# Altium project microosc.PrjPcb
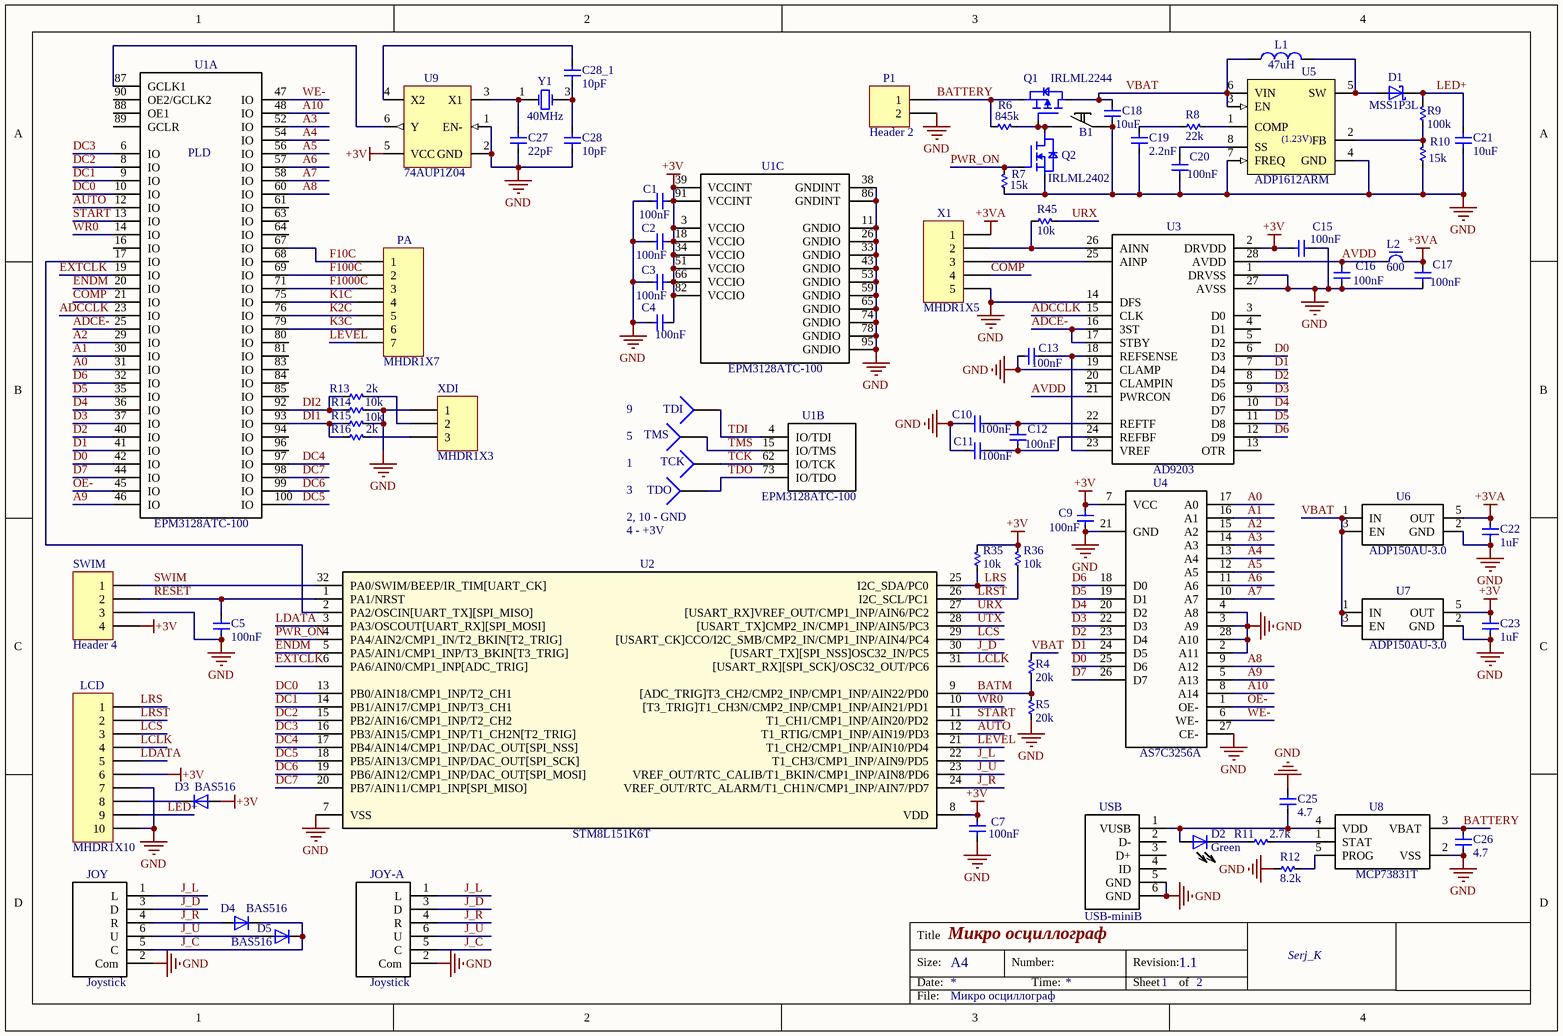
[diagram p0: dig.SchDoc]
2 sheets, 144 parts. Net scope: global (net labels, ports and power ports of the same name join across sheets).
Board file: microosc.PcbDoc
Sheets:
  dig.SchDoc
  analog.SchDoc

## Sheet dig.SchDoc: Микро осциллограф
size A4; Author: Serj_K; Engineer: Serj_K; Organization: Serj_K; Revision: 1.1; SheetNumber: 1; SheetTotal: 2; PageSetup: Record=PageOptions|CenterHorizontal=True|CenterVertical=True|PrintScale=1.00|XCorrection=1.00|YCorrection=1.00|PrintKind=0|BorderSize=5000000|LeftOffset=0|BottomOffset=0|Orientation=2|PaperLength=1000|PaperWidth=1000|Scale=100|PaperSource=7|PrintQuality=1200|MediaType=1|DitherType=10|PaperKind=A4|PrintScaleMode=1

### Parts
B1  Micro Button  [Micro Button]  (value not drawn)
C1  value 100nF  [C0603NH080]  (hidden comment: Cap)
C2  value 100nF  [C0603NH080]  (hidden comment: Cap)
C3  value 100nF  [C0603NH080]  (hidden comment: Cap)
C4  value 100nF  [C0603NH080]  (hidden comment: Cap)
C5  value 100nF  [C0603NH080]  (hidden comment: Cap)
C7  value 100nF  [C0603NH080]  (hidden comment: Cap)
C9  value 100nF  [C0603NH080]  (hidden comment: Cap)
C10  value 100nF  [C0603NH080]  (hidden comment: Cap)
C11  value 100nF  [C0603NH080]  (hidden comment: Cap)
C12  value 100nF  [C0603NH080]  (hidden comment: Cap)
C13  value 100nF  [C0603NH080]  (hidden comment: Cap)
C15  value 100nF  [C0603NH080]  (hidden comment: Cap)
C16  value 100nF  [C0603NH080]  (hidden comment: Cap)
C17  value 100nF  [C0603NH080]  (hidden comment: Cap)
C18  value 10uF  [C0805NH145]  (hidden comment: Cap)
C19  value 2.2nF  [C0805NH145]  (hidden comment: Cap)
C20  value 100nF  [C0603NH080]  (hidden comment: Cap)
C21  value 10uF  [C1206NH190]  (hidden comment: Cap)
C22  value 1uF  [C0805NH145]  (hidden comment: Cap)
C23  value 1uF  [C0805NH145]  (hidden comment: Cap)
C25  value 4.7  [C0805NH145]  (hidden comment: Cap)
C26  value 4.7  [C0805NH145]  (hidden comment: Cap)
C27  value 22pF  [C0603NH080]  (hidden comment: Cap)
C28  value 10pF  [C0603NH080]  (hidden comment: Cap)
C28_1  value 10pF  [C0603NH080]  (hidden comment: Cap)
D1  Part Label: MSS1P3L  [SOD323FL_VISHAY_MICROSMP]  (hidden comment: D_Schottky)
D2  Green  [SvetoDiod-D3]
D3  Part Label: BAS516  [SOD523]  (hidden comment: Diode)
D4  Part Label: BAS516  [SOD523]  (hidden comment: Diode)
D5  Part Label: BAS516  [SOD523]  (hidden comment: Diode)
JOY  Joystick  [Joystick]
JOY-A  Joystick  [Joystick]
L1  value 47uH  [L1212_muR_LQH3NP]  (hidden comment: L)
L2  value 600  [C0603NH080]  (hidden comment: BEAD)
LCD  MHDR1X10  [MHDR1X10]
P1  Header 2  [HDR1X2]
PA  MHDR1X7  [MHDR1X7]
Q1  IRLML2244  [SOT23-3_DISCRETE]
Q2  IRLML2402  [SOT23-3_DISCRETE]
R4  value 20k  [R0603N]  (hidden comment: R)
R5  value 20k  [R0603N]  (hidden comment: R)
R6  value 845k  [R0603N]  (hidden comment: R)
R7  value 15k  [R0603N]  (hidden comment: R)
R8  value 22k  [R0603N]  (hidden comment: R)
R9  value 100k  [R0603N]  (hidden comment: R)
R10  value 15k  [R0603N]  (hidden comment: R)
R11  value 2.7k  [R0805NH070]  (hidden comment: R)
R12  value 8.2k  [R0603N]  (hidden comment: R)
R13  value 2k  [R0603N]  (hidden comment: R)
R14  value 10k  [R0603N]  (hidden comment: R)
R15  value 10k  [R0603N]  (hidden comment: R)
R16  value 2k  [R0603N]  (hidden comment: R)
R35  value 10k  [R0603N]  (hidden comment: R)
R36  value 10k  [R0603N]  (hidden comment: R)
R45  value 10k  [R0603N]  (hidden comment: R)
SWIM  Header 4  [HDR1X4]
TCK  Socket  [PIN1]  (value not drawn)
TDI  Socket  [PIN1]  (value not drawn)
TDO  Socket  [PIN1]  (value not drawn)
TMS  Socket  [PIN1]  (value not drawn)
U1  EPM3128ATC-100  [TQFP100_N]  (parts A,B,C of 3)
U2  STM8L151K6T  [TQFP32_L]
U3  AD9203  [RS-28]
U4  AS7C3256A  [TSOP28]
U5  Part Label: ADP1612ARM  [MSOP8]  (hidden comment: ADP1612)
U6  ADP150AU-3.0  [RT-5]
U7  ADP150AU-3.0  [RT-5]
U8  MCP73831T  [S5]
U9  74AUP1Z04  [SC70-6]
USB  USB-miniB  [USB-B_CrossBoard]
X1  MHDR1X5  [MHDR1X5]
XDI  MHDR1X3  [MHDR1X3]
Y1  value 40MHz  [QUARZ_REC_25x32]  (hidden comment: Quarz Rezonator SMD)

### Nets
+3V: C1.2 C2.2 C3.2 C4.2 C7.2 C9.1 C15.2 C23.2 D3.A LCD.6 R35.2 R36.2 SWIM.4 U1.3(VCCIO) U1.18(VCCIO) U1.34(VCCIO) U1.39(VCCINT) U1.51(VCCIO) U1.66(VCCIO) U1.82(VCCIO) U1.91(VCCINT) U2.8(VDD) U3.2(DRVDD) U4.7(VCC) U7.5(OUT) U9.5(VCC)
+3VA: C17.1 C22.2 L2.2 U6.5(OUT) X1.1
GND: B1.1 C1.1 C2.1 C3.1 C4.1 C5.1 C7.1 C9.2 C10.1 C11.1 C13.1 C15.1 C16.2 C17.2 C18.1 C19.1 C20.2 C21.1 C22.1 C23.1 C25.2 C26.1 C27.1 C28.1 JOY.2(Com) JOY-A.2(Com) LCD.7 LCD.10 P1.2 Q2.2(S) R5.1 R7.1 R10.1 R12.1 R14.2 R15.2 SWIM.3 U1.11(GNDIO) U1.26(GNDIO) U1.33(GNDIO) U1.38(GNDINT) U1.43(GNDIO) U1.53(GNDIO) U1.59(GNDIO) U1.65(GNDIO) U1.74(GNDIO) U1.78(GNDIO) U1.86(GNDINT) U1.95(GNDIO) U2.7(VSS) U3.1(DRVSS) U3.14(DFS) U3.19(CLAMP) U3.27(AVSS) U4.2(A11) U4.3(A9) U4.4(A8) U4.21(GND) U4.27(CE-) U4.28(A10) U5.4(GND) U5.7(FREQ) U6.2(GND) U7.2(GND) U8.2(VSS) U9.1(EN-) U9.2(GND) USB.5(GND) USB.6(GND) X1.5 XDI.1
A0: U1.31(IO) U4.17(A0)
A1: U1.30(IO) U4.16(A1)
A2: U1.29(IO) U4.15(A2)
A3: U1.52(IO) U4.14(A3)
A4: U1.54(IO) U4.13(A4)
A5: U1.56(IO) U4.12(A5)
A6: U1.57(IO) U4.11(A6)
A7: U1.58(IO) U4.10(A7)
A8: U1.60(IO) U4.9(A12)
A9: U1.46(IO) U4.5(A13)
A10: U1.48(IO) U4.8(A14)
ADCCLK: U1.23(IO) U3.15(CLK)
ADCE-: U1.25(IO) U3.16(3ST) U3.17(STBY)
AUTO: U1.12(IO) U2.12(T1_RTIG/CMP1_INP/AIN19/PD3)
AVDD: C16.1 L2.1 U3.21(PWRCON) U3.28(AVDD)
BATM: R4.1 R5.2 U2.9([ADC_TRIG]T3_CH2/CMP2_INP/CMP1_INP/AIN22/PD0)
BATTERY: C26.2 P1.1 Q1.2(S) R6.1 U8.3(VBAT)
COMP: U1.21(IO) X1.4
D0: U1.42(IO) U3.6(D3) U4.25(D6)
D1: U1.41(IO) U3.7(D4) U4.24(D5)
D2: U1.40(IO) U3.8(D5) U4.23(D4)
D3: U1.37(IO) U3.9(D6) U4.22(D3)
D4: U1.36(IO) U3.10(D7) U4.20(D2)
D5: U1.35(IO) U3.11(D8) U4.19(D1)
D6: U1.32(IO) U3.12(D9) U4.18(D0)
D7: U1.44(IO) U4.26(D7)
DC0: U1.10(IO) U2.13(PB0/AIN18/CMP1_INP/T2_CH1)
DC1: U1.9(IO) U2.14(PB1/AIN17/CMP1_INP/T3_CH1)
DC2: U1.8(IO) U2.15(PB2/AIN16/CMP1_INP/T2_CH2)
DC3: U1.6(IO) U2.16(PB3/AIN15/CMP1_INP/T1_CH2N[T2_TRIG])
DC4: U1.97(IO) U2.17(PB4/AIN14/CMP1_INP/DAC_OUT[SPI_NSS])
DC5: U1.100(IO) U2.18(PB5/AIN13/CMP1_INP/DAC_OUT[SPI_SCK])
DC6: U1.99(IO) U2.19(PB6/AIN12/CMP1_INP/DAC_OUT[SPI_MOSI])
DC7: U1.98(IO) U2.20(PB7/AIN11/CMP1_INP[SPI_MISO])
DI1: R15.1 R16.1 U1.93(IO)
DI2: R13.1 R14.1 U1.92(IO)
ENDM: U1.20(IO) U2.5(PA5/AIN1/CMP1_INP/T3_BKIN[T3_TRIG])
EXTCLK: U1.19(IO) U2.6(PA6/AIN0/CMP1_INP[ADC_TRIG])
F10C: PA.1 U1.67(IO)
F100C: PA.2 U1.69(IO)
F1000C: PA.3 U1.71(IO)
J_C: D4.C D5.C JOY.5(C) JOY-A.5(C)
J_D: JOY.3(D) JOY-A.3(D) U2.30([USART_TX][SPI_NSS]OSC32_IN/PC5)
J_L: JOY.1(L) JOY-A.1(L) U2.22(T1_CH3/CMP1_INP/AIN9/PD5)
J_R: D4.A JOY.4(R) JOY-A.4(R) U2.24(VREF_OUT/RTC_ALARM/T1_CH1N/CMP1_INP/AIN7/PD7)
J_U: D5.A JOY.6(U) JOY-A.6(U) U2.23(VREF_OUT/RTC_CALIB/T1_BKIN/CMP1_INP/AIN8/PD6)
K1C: PA.4 U1.75(IO)
K2C: PA.5 U1.76(IO)
K3C: PA.6 U1.79(IO)
LCLK: LCD.4 U2.31([USART_RX][SPI_SCK]/OSC32_OUT/PC6)
LCS: LCD.3 U2.29([USART_CK]CCO/I2C_SMB/CMP2_IN/CMP1_INP/AIN4/PC4)
LDATA: LCD.5 U2.3(PA3/OSCOUT[UART_RX][SPI_MOSI])
LED+: C21.2 D1.C LCD.9 R9.2
LEVEL: PA.7 U2.21(T1_CH2/CMP1_INP/AIN10/PD4)
LRS: LCD.1 R35.1 U2.25(I2C_SDA/PC0)
LRST: LCD.2 R36.1 U2.26(I2C_SCL/PC1)
OE-: U1.45(IO) U4.1(OE-)
PWR_ON: Q2.1(G) R7.2 U2.4(PA4/AIN2/CMP1_IN/T2_BKIN[T2_TRIG])
RESET: C5.2 SWIM.2 U2.1(PA1/NRST)
START: U1.13(IO) U2.11(T1_CH1/CMP1_INP/AIN20/PD2)
SWIM: SWIM.1 U2.32(PA0/SWIM/BEEP/IR_TIM[UART_CK])
TCK: TCK.1 U1.62(IO/TCK)
TDI: TDI.1 U1.4(IO/TDI)
TDO: TDO.1 U1.73(IO/TDO)
TMS: TMS.1 U1.15(IO/TMS)
URX: R45.2 U2.27([USART_RX]VREF_OUT/CMP1_INP/AIN6/PC2)
UTX: U2.28([USART_TX]CMP2_IN/CMP1_INP/AIN5/PC3)
VBAT: C18.2 L1.1 Q1.3(D) R4.2 U5.3(EN) U5.6(VIN) U6.1(IN) U6.3(EN) U7.1(IN) U7.3(EN)
WE-: U1.47(IO) U4.6(WE-)
WR0: U1.14(IO) U2.10([T3_TRIG]T1_CH3N/CMP2_INP/CMP1_INP/AIN21/PD1)
NetB1_2: B1.2 Q1.1(G) Q2.3(D) R6.2
NetC10_2: C10.2 C12.2 U3.22(REFTF)
NetC11_2: C11.2 C12.1 U3.24(REFBF)
NetC13_2: C13.2 U3.18(REFSENSE) U3.23(VREF)
NetC19_2: C19.2 R8.1
NetC20_1: C20.1 U5.8(SS)
NetC25_1: C25.1 D2.A U8.4(VDD) USB.1(VUSB)
NetC27_2: C27.2 U9.3(X1) Y1.1(OSC1)
NetC28_1_1: C28_1.1 U9.4(X2)
NetC28_2: C28.2 C28_1.2 Y1.3(OSC2)
NetD1_A: D1.A L1.2 U5.5(SW)
NetD2_K: D2.K R11.1
NetD3_C: D3.C LCD.8
NetR8_2: R8.2 U5.1(COMP)
NetR9_1: R9.1 R10.2 U5.2(FB)
NetR11_2: R11.2 U8.1(STAT)
NetR12_2: R12.2 U8.5(PROG)
NetR13_2: R13.2 XDI.2
NetR16_2: R16.2 XDI.3
NetR45_1: R45.1 U3.26(AINN) X1.2
NetU1_17: U1.17(IO) U2.2(PA2/OSCIN[UART_TX][SPI_MISO])
NetU1_87: U1.87(GCLK1) U9.6(Y)
NetU3_25: U3.25(AINP) X1.3

Not connected (* = marked no-connect by the designer): U1 16(IO) 61(IO) 63(IO) 64(IO) 68(IO) 80(IO) 81(IO) 83(IO) 84(IO) 85(IO) 88(OE1) 89(GCLR) 90(OE2/GCLK2) 94(IO) 96(IO); U3 3(D0) 4(D1) 5(D2) 13(OTR) 20(CLAMPIN); USB 2(D-) 3(D+) 4(ID)

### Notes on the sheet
- 9
- 5
- 1
- 3
- (near TDO) 2, 10 - GND
- 4 - +3V

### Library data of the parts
C1-C5 C7 C9-C13 C15-C17 C20 = CL10B104KB8NNNC: PartName: CL10; Part Label: C0603 100nF 10% X7R 50V; Manufacturer: Samsung Electro-Mechanics; Voltage: 50V; Tolerance: 10 %; Device: C; ShortName: C0603
C18 = GRM21BR61A106KE19L: PartName: GRM21; Part Label: C0805 10uF 10% X5R 10V; Manufacturer: muRata; Voltage: 10V; Tolerance: 10 %; Device: C; ShortName: C0805
C19 = CL21C222JBFNNNE: PartName: CL21; Part Label: C0805 2.2nF 5% NP0 50V; Manufacturer: Samsung Electro-Mechanics; Voltage: 50V; Tolerance: 5 %; Device: C; ShortName: C0805
C21 = GRM31CR61E106KA12L: PartName: GRM31; Part Label: C1206 10uF 10% X5R 25V; Manufacturer: muRata; Voltage: 25V; Tolerance: 10 %; Device: C; ShortName: C1206
C22 C23 C25 C26 = GRM21BR71H105KA12L: PartName: GRM21; Part Label: C0805 1uF 10% X7R 50V; Manufacturer: muRata; Voltage: 50V; Tolerance: 10 %; Device: C; ShortName: C0805
C27 C28 C28_1 = CL10C220JB8NNNC: PartName: CL10; Part Label: C0603 22pF 5% NP0 50V; Manufacturer: Samsung Electro-Mechanics; Voltage: 50V; Tolerance: 5 %; Device: C; ShortName: C0603
D1 = MSS1P3L-M3/89A: 30V, 1A, eSMP, Surface Mount Schottky Barrier Rectifiers; PartName: MSSXPXX; Manufacturer: Vishay; ClassName_u: Schottky SMD; Device: D
D2 = Svetodiod: Lite Diode
D3-D5 = BAS516,115: High-speed switching diodes; Manufacturer: NXP Semiconductors; ClassName_u: Switching SMD; Device: D
L1 = LQH3NPN470MM0L: Shielded Power Inductor Wire Wound; Part Label: L1212 47uH 20% 0.31A; Manufacturer: muRata; Tolerance: 20 %; ShortName: L1212
L2 = BLM18KG601SN1D: High performance type for power lines up to 600ohm.; Part Label: SMD Beads 600 1.3A; Manufacturer: muRata; Device: EMI; ShortName: SMD Beads
LCD = MHDR1X10: Header, 10-Pin
P1 = Header 2: Header, 2-Pin
PA = MHDR1X7: Header, 7-Pin
Q1 = IRLML2244TRPBF: 20V, 4.3A Single P-Channel HEXFET Power MOSFET; Manufacturer: International Rectifier; Device: Q; ShortName: PMOS
Q2 = IRLML2402TRPBF: 20V, 0.25 Ohm, Single N-Channel HEXFET Power MOSFET; Manufacturer: International Rectifier; Device: Q; ShortName: NMOS
R4 R5 = 0603SAF2002T50: PartName: 0603SA; Part Label: R0603 20k 1% TC100 50V; Manufacturer: uniOhm; TempCo: 100 ppm; Tolerance: 1 %; ShortName: R0603
R6 = ERJ3EKF8453V: PartName: ERJ3E; Part Label: R0603 845k 1% TC100 50V; Manufacturer: Panasonic; TempCo: 100 ppm; Tolerance: 1 %; ShortName: R0603
R7 R10 = 0603SAF1501T50: PartName: 0603SA; Part Label: R0603 15k 1% TC100 50V; Manufacturer: uniOhm; TempCo: 100 ppm; Tolerance: 1 %; ShortName: R0603
R8 = 0603SAF2202T50: PartName: 0603SA; Part Label: R0603 22k 1% TC100 50V; Manufacturer: uniOhm; TempCo: 100 ppm; Tolerance: 1 %; ShortName: R0603
R9 = 0603SAF1003T50: PartName: 0603SA; Part Label: R0603 100k 1% TC100 50V; Manufacturer: uniOhm; TempCo: 100 ppm; Tolerance: 1 %; ShortName: R0603
R11 = 0805S8F2701T50: PartName: 0805S; Part Label: R0805 2.7k 1% TC100 150V; Manufacturer: uniOhm; TempCo: 100 ppm; Tolerance: 1 %; ShortName: R0805
R12 = 0603SAF8201T50: PartName: 0603SA; Part Label: R0603 8.2k 1% TC100 50V; Manufacturer: uniOhm; TempCo: 100 ppm; Tolerance: 1 %; ShortName: R0603
R13 R16 = 0603SAF2001T50: PartName: 0603SA; Part Label: R0603 2k 1% TC100 50V; Manufacturer: uniOhm; TempCo: 100 ppm; Tolerance: 1 %; ShortName: R0603
R14 R15 R35 R36 R45 = 0603SAF1002T50: PartName: 0603SA; Part Label: R0603 10k 1% TC100 50V; Manufacturer: uniOhm; TempCo: 100 ppm; Tolerance: 1 %; ShortName: R0603
SWIM = Header 4: Header, 4-Pin
U1 = EPM3064ATC-100
U2 = STM8L151Kn
U5 = ADP1612ARMZ-R7: 20 V, 650 kHz/1.3 MHz Step-Up PWM DCDC Switching Converter; Manufacturer: Analog Devices, Inc; ClassName_u: Power ICs; Device: U
U6 U7 = ADP150AU: LDO
U8 = MCP73831T: Li-Ion battery charger
U9 = 74AUP1Z04GW,125: Low-power X-tal driver with enable and internal resistor; Manufacturer: NXP Semiconductors; ClassName_u: Logic; Device: U
USB = USB
X1 = MHDR1X5: Header, 5-Pin
XDI = MHDR1X3: Header, 3-Pin

## Sheet analog.SchDoc: Микро осциллограф
size A4; Organization: Serj_K; Revision: 1.1; SheetNumber: 2; SheetTotal: 2; PageSetup: Record=PageOptions|CenterHorizontal=True|CenterVertical=True|PrintScale=1.00|XCorrection=1.00|YCorrection=1.00|PrintKind=0|BorderSize=5000000|LeftOffset=0|BottomOffset=0|Orientation=2|PaperLength=2970|PaperWidth=2100|Scale=100|PaperSource=7|PrintQuality=600|MediaType=1|DitherType=10|PaperKind=A4|PrintScaleMode=1
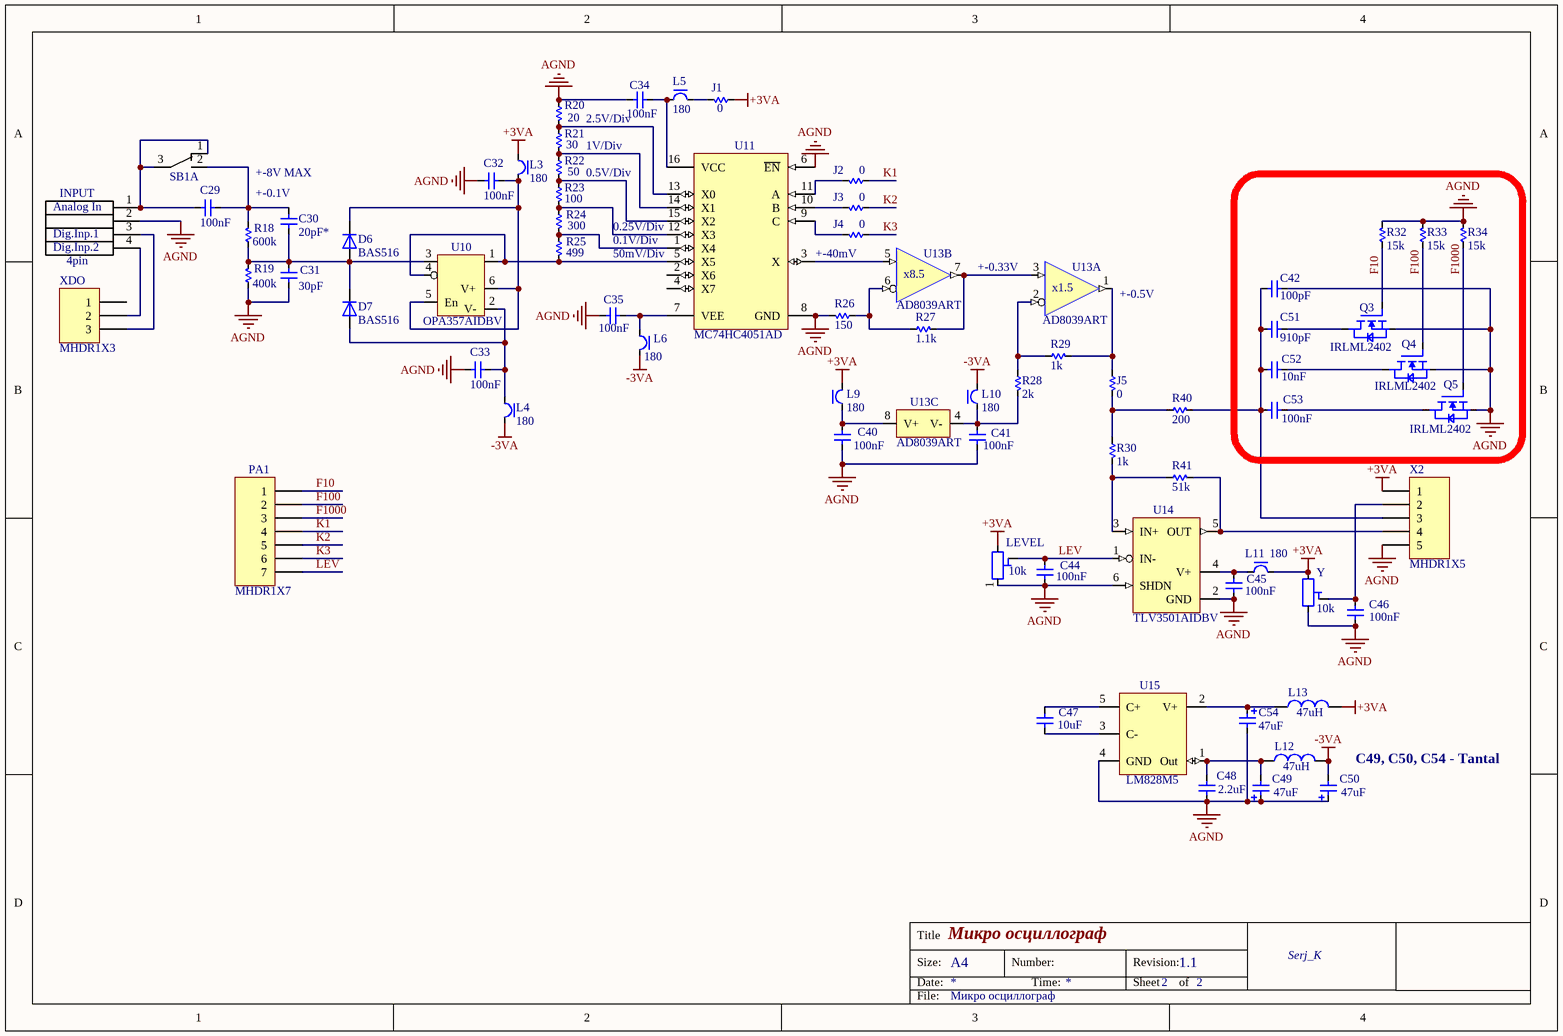
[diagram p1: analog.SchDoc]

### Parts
C29  value 100nF  [C0603NH080]  (hidden comment: Cap)
C30  value 20pF*  [C0805NH145]  (hidden comment: Cap)
C31  value 30pF  [C0603NH080]  (hidden comment: Cap)
C32  value 100nF  [C0603NH080]  (hidden comment: Cap)
C33  value 100nF  [C0603NH080]  (hidden comment: Cap)
C34  value 100nF  [C0603NH080]  (hidden comment: Cap)
C35  value 100nF  [C0603NH080]  (hidden comment: Cap)
C40  value 100nF  [C0603NH080]  (hidden comment: Cap)
C41  value 100nF  [C0603NH080]  (hidden comment: Cap)
C42  value 100pF  [C0603NH080]  (hidden comment: Cap)
C44  value 100nF  [C0603NH080]  (hidden comment: Cap)
C45  value 100nF  [C0603NH080]  (hidden comment: Cap)
C46  value 100nF  [C0603NH080]  (hidden comment: Cap)
C47  value 10uF  [C0805NH145]  (hidden comment: Cap)
C48  value 2.2uF  [C0603NH080]  (hidden comment: Cap)
C49  value 47uF  [CAPMP3528X210N_KEMET]  (hidden comment: ECap)
C50  value 47uF  [CAPMP3528X210N_KEMET]  (hidden comment: ECap)
C51  value 910pF  [C0603NH080]  (hidden comment: Cap)
C52  value 10nF  [C0603NH080]  (hidden comment: Cap)
C53  value 100nF  [C0603NH080]  (hidden comment: Cap)
C54  value 47uF  [CAPMP3528X210N_KEMET]  (hidden comment: ECap)
D6  Part Label: BAS516  [SOD523]  (hidden comment: Diode)
D7  Part Label: BAS516  [SOD523]  (hidden comment: Diode)
INPUT  4pin  [4pin_2.5_Audio]
J1  value 0  [R1206NH084]  (hidden comment: R)
J2  value 0  [R1206NH084]  (hidden comment: R)
J3  value 0  [R1206NH084]  (hidden comment: R)
J4  value 0  [R1206NH084]  (hidden comment: R)
J5  value 0  [R1206NH084]  (hidden comment: R)
L3  value 180  [C0603NH080]  (hidden comment: BEAD)
L4  value 180  [C0603NH080]  (hidden comment: BEAD)
L5  value 180  [C0603NH080]  (hidden comment: BEAD)
L6  value 180  [C0603NH080]  (hidden comment: BEAD)
L9  value 180  [C0805NH145]  (hidden comment: BEAD)
L10  value 180  [C0603NH080]  (hidden comment: BEAD)
L11  value 180  [C0603NH080]  (hidden comment: BEAD)
L12  value 47uH  [L1210_muR_LQH32]  (hidden comment: L)
L13  value 47uH  [L1210_muR_LQH32]  (hidden comment: L)
LEVEL  value 10k  [CA6H]  (hidden comment: Res_Var)
PA1  MHDR1X7  [MHDR1X7]
Q3  IRLML2402  [SOT23-3_DISCRETE]
Q4  IRLML2402  [SOT23-3_DISCRETE]
Q5  IRLML2402  [SOT23-3_DISCRETE]
R18  value 600k  [R0603N]  (hidden comment: R)
R19  value 400k  [R0603N]  (hidden comment: R)
R20  value 20  [R0603N]  (hidden comment: R)
R21  value 30  [R0603N]  (hidden comment: R)
R22  value 50  [R0603N]  (hidden comment: R)
R23  value 100  [R0603N]  (hidden comment: R)
R24  value 300  [R0603N]  (hidden comment: R)
R25  value 499  [R0603N]  (hidden comment: R)
R26  value 150  [R0603N]  (hidden comment: R)
R27  value 1.1k  [R0603N]  (hidden comment: R)
R28  value 2k  [R0603N]  (hidden comment: R)
R29  value 1k  [R0603N]  (hidden comment: R)
R30  value 1k  [R0603N]  (hidden comment: R)
R32  value 15k  [R0603N]  (hidden comment: R)
R33  value 15k  [R0603N]  (hidden comment: R)
R34  value 15k  [R0603N]  (hidden comment: R)
R40  value 200  [R0805NH070]  (hidden comment: R)
R41  value 51k  [R0603N]  (hidden comment: R)
SB1  SB_8x8  [SB_8x8]  (value not drawn)  (part A of 2)
U10  OPA357AIDBV  [SOT23-6RR]
U11  MC74HC4051AD  [751B-05_N]
U13  Part Label: AD8039ART  [TSOT23-8]  (hidden comment: AD8039)  (parts A,B,C of 3)
U14  TLV3501AIDBV  [SOT23-6RR]
U15  Part Label: LM828M5  [SOT23-5]  (hidden comment: LM828)
X2  MHDR1X5  [MHDR1X5]
XDO  MHDR1X3  [MHDR1X3]
Y  value 10k  [CA6H]  (hidden comment: Res_Var)

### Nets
+3VA: J1.1 L3.1 L9.2 L11.2 L13.2 LEVEL.2 X2.1 Y.1
-3VA: C50.C L4.2 L6.2 L10.2 L12.2
AGND: C31.1 C32.1 C33.1 C34.1 C35.1 C40.2 C41.2 C42.2 C44.2 C45.2 C46.2 C48.1 C49.A C50.A C54.C INPUT.2 LEVEL.1 Q3.2(S) Q4.2(S) Q5.2(S) R19.1 R20.1 R26.2 R32.2 R33.2 R34.2 U11.6(~{EN}) U11.8(GND) U14.2(GND) U14.6(SHDN) U15.4(GND) X2.5 Y.2
F10: PA1.1 Q3.1(G) R32.1
F100: PA1.2 Q4.1(G) R33.1
F1000: PA1.3 Q5.1(G) R34.1
K1: J2.1 PA1.4
K2: J3.1 PA1.5
K3: J4.1 PA1.6
LEV: C44.1 LEVEL.3 PA1.7 U14.1(IN-)
NetC29_1: C29.1 INPUT.1 SB1.1 SB1.3
NetC29_2: C29.2 C30.2 R18.2 SB1.2
NetC30_1: C30.1 C31.2 D6.A D7.C R18.1 R19.2 U10.3(In+)
NetC32_2: C32.2 D6.C L3.2 U10.5(En) U10.6(V+)
NetC33_2: C33.2 D7.A L4.1 U10.2(V-)
NetC34_2: C34.2 L5.1 U11.16(VCC)
NetC35_2: C35.2 L6.1 U11.7(VEE)
NetC40_1: C40.1 L9.1 U13.8(V+)
NetC41_1: C41.1 L10.1 R28.2 U13.4(V-)
NetC42_1: C42.1 C51.1 C52.1 C53.1 R40.2 X2.3
NetC45_1: C45.1 L11.1 U14.4(V+)
NetC46_1: C46.1 X2.2 Y.3
NetC47_1: C47.1 U15.3(C-)
NetC47_2: C47.2 U15.5(C+)
NetC48_2: C48.2 C49.C L12.1 U15.1(Out)
NetC51_2: C51.2 Q3.3(D)
NetC52_2: C52.2 Q4.3(D)
NetC53_2: C53.2 Q5.3(D)
NetC54_A: C54.A L13.1 U15.2(V+)
NetINPUT_3: INPUT.3 XDO.3
NetINPUT_4: INPUT.4 XDO.2
NetJ1_2: J1.2 L5.2
NetJ2_2: J2.2 U11.11(A)
NetJ3_2: J3.2 U11.10(B)
NetJ4_2: J4.2 U11.9(C)
NetJ5_1: J5.1 R29.2 U13.1(Out)
NetJ5_2: J5.2 R30.1 R40.1
NetR20_2: R20.2 R21.1 U11.13(X0)
NetR21_2: R21.2 R22.1 U11.14(X1)
NetR22_2: R22.2 R23.1 U11.15(X2)
NetR23_2: R23.2 R24.1 U11.12(X3)
NetR24_2: R24.2 R25.1 U11.1(X4)
NetR25_2: R25.2 U10.1(Out) U10.4(In-) U11.5(X5)
NetR26_1: R26.1 R27.1 U13.6(In-)
NetR27_2: R27.2 U13.3(In) U13.7(Out)
NetR28_1: R28.1 R29.1 U13.2(In-)
NetR30_2: R30.2 R41.1 U14.3(IN+)
NetR41_2: R41.2 U14.5(OUT) X2.4
NetU11_3: U11.3(X) U13.5(In)

Not connected (* = marked no-connect by the designer): U11 2(X6) 4(X7); XDO 1

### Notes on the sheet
- +-8V MAX
- 0.5V/Div
- 1V/Div
- (near C34) 2.5V/Div
- (near INPUT) Analog In
- (near INPUT) Dig.Inp.1
- (near INPUT) Dig.Inp.2
- (near C30) +-0.1V
- (near U11) 0.1V/Div
- (near U11) 0.25V/Div
- (near U11) 50mV/Div
- (near J4) +-40mV
- (near U13) x8.5
- (near U13) +-0.33V
- (near U13) x1.5
- (near U13) +-0.5V
- C49, C50, C54 - Tantal

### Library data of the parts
C29 C32-C35 C40 C41 C44-C46 = CL10B104KB8NNNC: as C1 on sheet dig
C30 = CL21C220JBANNNC: PartName: CL21; Part Label: C0805 22pF 5% NP0 50V; Manufacturer: Samsung Electro-Mechanics; Voltage: 50V; Tolerance: 5 %; Device: C; ShortName: C0805
C31 = CL10C470JB8NNNC: PartName: CL10; Part Label: C0603 47pF 5% NP0 50V; Manufacturer: Samsung Electro-Mechanics; Voltage: 50V; Tolerance: 5 %; Device: C; ShortName: C0603
C42 C51-C53 = C0603C151J5GAC7867: PartName: C0603C; Part Label: C0603 150pF 5% NP0 50V; Manufacturer: Kemet; Voltage: 50V; Tolerance: 5 %; Device: C; ShortName: C0603
C47 = GRM21BR61A106KE19L: as C18 on sheet dig
C48 = GRM188R61C225KE15D: PartName: GRM188; Part Label: C0603 2.2uF 10% X5R 16V; Manufacturer: muRata; Voltage: 16V; Tolerance: 10 %; Device: C; ShortName: C0603
C49 C50 C54 = T520B476M006ATE040: T520 Series Polymer Tantalum 40mOhm; PartName: T520B; Part Label: SMD Tantal 47uF 20% 6V 1.8A; Manufacturer: Kemet; Voltage: 6V; Tolerance: 20 %; ClassName_u: SMD Tantal; Device: C
D6 D7 = BAS516,115: as D3 on sheet dig
J1-J5 = 12064SF1000T50: PartName: 1206SF; Part Label: R1206 100 1% TC100 200V; Manufacturer: uniOhm; TempCo: 100 ppm; Tolerance: 1 %; ShortName: R1206
L3-L6 L10 L11 = BLM18PG181SN1D: Bead 0603 size for power lines; Part Label: SMD Beads 180 1.5A; Manufacturer: muRata; Device: EMI; ShortName: SMD Beads
L9 = BLM21PG331SN1D: Bead 0805 size for power lines; Part Label: SMD Beads 330 1.5A; Manufacturer: muRata; Device: EMI; ShortName: SMD Beads
L12 L13 = LQH32CN220K23L: Power Inductor Wire Wound; PartName: LQH32C; Part Label: L1210 22uH 10% 0.47A; Manufacturer: muRata; Tolerance: 10 %; ShortName: L1210
LEVEL Y = Res_Var: Variable resistor
PA1 = MHDR1X7: Header, 7-Pin
Q3-Q5 = IRLML2402TRPBF: as Q2 on sheet dig
R18 R19 = 0603SAF3003T50: PartName: 0603SA; Part Label: R0603 300k 1% TC100 50V; Manufacturer: uniOhm; TempCo: 100 ppm; Tolerance: 1 %; ShortName: R0603
R20 = 0603SAF1000T50: PartName: 0603SA; Part Label: R0603 100 1% TC100 50V; Manufacturer: uniOhm; TempCo: 100 ppm; Tolerance: 1 %; ShortName: R0603
R21 R26-R28 = 0603SAF2701T50: PartName: 0603SA; Part Label: R0603 2.7k 1% TC100 50V; Manufacturer: uniOhm; TempCo: 100 ppm; Tolerance: 1 %; ShortName: R0603
R22 R23 = 0603SAF5102T50: PartName: 0603SA; Part Label: R0603 51k 1% TC100 50V; Manufacturer: uniOhm; TempCo: 100 ppm; Tolerance: 1 %; ShortName: R0603
R24 = TC0350F4023T5E: TC03 (0603) 1/16W 1% 402K 50PPM T/R-5000; Part Label: R0603 402k 1% TC50 50V; Manufacturer: uniOhm; ClassName_u: SMD 0603 Thin Film; ShortName: R0603
R25 = 0603SAF5103T50: PartName: 0603SA; Part Label: R0603 510k 1% TC100 50V; Manufacturer: uniOhm; TempCo: 100 ppm; Tolerance: 1 %; ShortName: R0603
R29 R30 R32-R34 R41 = 0603SAF1501T50: as R7 on sheet dig
R40 = RR1220Q-100-D: PartName: RR1220; Part Label: R0805 10 0.5% TC50 100V; Manufacturer: SUSUMU; TempCo: 50 ppm; Tolerance: 0.5 %; ClassName_u: SMD 0805 Thin Film; ShortName: R0805
U10 = OPA357AIDBVR: 250MHz, RRIO, CMOS Operational Amplifier with Shutdown; PartName: OPA357xxDBV; Manufacturer: Texas Instruments; ClassName_u: Amplifiers; Device: U
U11 = MC74HC4051AD: Analog Multiplexer/Demultiplexer
U13 = AD8039ARTZ-REEL7: Dual, Low Power 350MHz, Voltage Feedback Amplifiers; Manufacturer: Analog Devices, Inc; Device: U
U14 = TLV3501AIDBVR: 4.5ns Rail-to-Rail, High-Speed Comparator; PartName: TLV3501xxDBV; Manufacturer: Texas Instruments; ClassName_u: Comparators; Device: U
U15 = LM828M5: Switched Capacitor Voltage Converter; Manufacturer: National Semiconductor Corporation; ClassName_u: Power ICs; Device: U
X2 = MHDR1X5: Header, 5-Pin
XDO = MHDR1X3: Header, 3-Pin

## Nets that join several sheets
+3VA: dig (5 pins), analog (8 pins)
